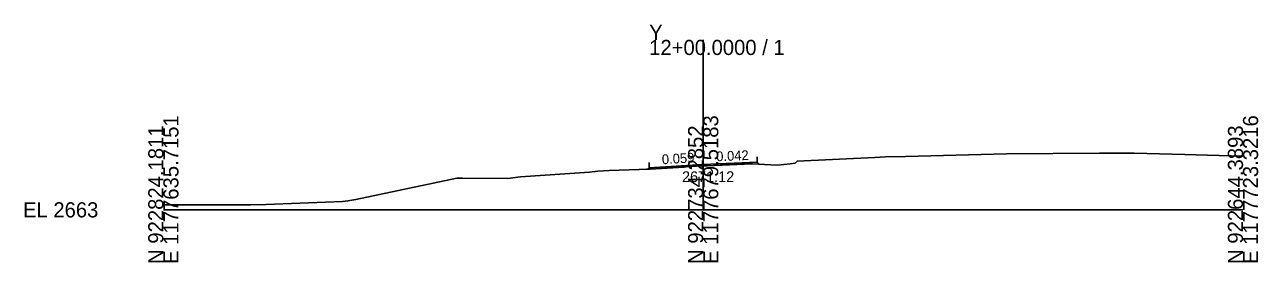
# Model space of a CAD drawing. Extents: x -26 to 203, y -10 to 2034.
# Drawn here: x -25.7 to 202.8, y 1990.3 to 2034.2 of the extents above; entities that cross this region are included whole.
import ezdxf

# ---------------------------------------------------------------- set-up
doc = ezdxf.new("R2010")
doc.units = 0
for name, color, linetype in [('Exist Cross Section Cell', 7, 'Continuous'), ('Exist XS Center Line Elevation Label', 7, 'Continuous'), ('Exist XS Ground Line', 7, 'Continuous'), ('Prop XS Dump Level', 7, 'Continuous'), ('Prop XS EOT Tick Mark', 7, 'Continuous'), ('Prop XS Finish Grade Pavement', 7, 'Continuous'), ('Prop XS Pvmt Edge Slope', 7, 'Continuous'), ('Prop XS SE Text', 7, 'Continuous'), ('Prop XS Wedging', 7, 'Continuous')]:
    doc.layers.add(name, color=color, linetype=linetype)

msp = doc.modelspace()

# ---------------------------------------------------------------- linework, layer by layer
at = {"layer": 'Exist Cross Section Cell'}
for p, q in [((100, 2000), (100, 2031.42)), ((0, 2000), (100, 2000)), ((100, 2000), (200, 2000))]:
    msp.add_line(p, q, dxfattribs=at)
at = {"layer": 'Exist XS Ground Line'}
for p, q in [((117.07, 2008.65), (117.41, 2008.98)), ((117.41, 2008.98), (131.8, 2009.7)), ((131.8, 2009.7), (133.79, 2009.79)), ((133.79, 2009.79), (137.47, 2009.87)), ((137.47, 2009.87), (156.21, 2010.35)), ((156.21, 2010.35), (173.42, 2010.47)), ((173.42, 2010.47), (179.84, 2010.45)), ((179.84, 2010.45), (189.2, 2010.22)), ((189.2, 2010.22), (193.41, 2010.12)), ((193.41, 2010.12), (200, 2009.95)), ((66.15, 2006.13), (78.92, 2006.97)), ((78.92, 2006.97), (80.5, 2007.13)), ((80.5, 2007.13), (82.61, 2007.25)), ((82.61, 2007.25), (88.15, 2007.45)), ((88.15, 2007.45), (89.48, 2007.5)), ((89.48, 2007.5), (90.16, 2007.54)), ((90.16, 2007.54), (99.73, 2008.11)), ((99.73, 2008.11), (100.72, 2008.15)), ((100.72, 2008.15), (109.1, 2008.5)), ((109.1, 2008.5), (112.56, 2008.32)), ((112.56, 2008.32), (113.77, 2008.24)), ((113.77, 2008.24), (116.13, 2008.52)), ((116.13, 2008.52), (117.07, 2008.65)), ((35.66, 2001.94), (54.37, 2005.84)), ((54.37, 2005.84), (55.39, 2005.88)), ((55.39, 2005.88), (63.84, 2005.81)), ((63.84, 2005.81), (66.15, 2006.13)), ((0, 2000.9), (15.05, 2000.9)), ((15.05, 2000.9), (16.13, 2000.91)), ((16.13, 2000.91), (19.07, 2001.01)), ((19.07, 2001.01), (20.61, 2001.06)), ((20.61, 2001.06), (33.19, 2001.53)), ((33.19, 2001.53), (34.17, 2001.68)), ((34.17, 2001.68), (35.66, 2001.94))]:
    msp.add_line(p, q, dxfattribs=at)
at = {"layer": 'Prop XS Dump Level'}
for p, q in [((90, 2007.78), (100, 2008.37)), ((100, 2008.37), (110, 2008.79))]:
    msp.add_line(p, q, dxfattribs=at)
at = {"layer": 'Prop XS EOT Tick Mark'}
for p, q in [((110, 2008.79), (110, 2009.79)), ((90, 2007.78), (90, 2008.78))]:
    msp.add_line(p, q, dxfattribs=at)
at = {"layer": 'Prop XS Finish Grade Pavement'}
for p, q in [((90, 2007.78), (100, 2008.37)), ((100, 2008.37), (110, 2008.79))]:
    msp.add_line(p, q, dxfattribs=at)
at = {"layer": 'Prop XS Pvmt Edge Slope'}
for p, q in [((90, 2007.78), (89.74, 2007.51)), ((110, 2008.79), (110.35, 2008.43))]:
    msp.add_line(p, q, dxfattribs=at)
at = {"layer": 'Prop XS Wedging'}
for points in [[(89.48, 2007.5), (89.48, 2007.5), (90.16, 2007.54), (96.45, 2007.91), (96.45, 2007.91), (90.16, 2007.54)], [(100.58, 2008.14), (100.72, 2008.15), (109.1, 2008.56), (109.1, 2008.5), (100.72, 2008.15)]]:
    msp.add_lwpolyline(points, close=True, dxfattribs=at)

# ---------------------------------------------------------------- texts
at = {"layer": 'Exist Cross Section Cell'}
for s, p in [('Y', (90, 2031.42)), ('12+00.0000 / 1', (90, 2028.62)), ('EL 2663', (-26, 1998.6))]:
    msp.add_text(s, height=2.8, dxfattribs=at).set_placement(p)
for s, p in [('E 1177635.7151', (2.8, 1990)), ('E 1177679.5183', (102.8, 1990)), ('E 1177723.3216', (202.8, 1990)), ('N 922824.1811', (0, 1990)), ('N 922734.2852', (100, 1990)), ('N 922644.3893', (200, 1990))]:
    msp.add_text(s, height=2.8, rotation=90, dxfattribs=at).set_placement(p)
at = {"layer": 'Exist XS Center Line Elevation Label'}
msp.add_text('2671.12', height=2, dxfattribs=at).set_placement((96.08, 2005.12))
at = {"layer": 'Prop XS Dump Level'}
msp.add_text('Case1', height=0.04, dxfattribs=at).set_placement((114, 2008.54))
at = {"layer": 'Prop XS SE Text'}
for s, rotation, p in [('0.059', 3.3765, (92.4, 2008.42)), ('0.042', 2.405, (102.45, 2008.97))]:
    msp.add_text(s, height=1.8, rotation=rotation, dxfattribs=at).set_placement(p)

doc.saveas('drawing.dxf')
